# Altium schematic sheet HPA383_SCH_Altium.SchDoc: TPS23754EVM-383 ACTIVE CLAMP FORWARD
size 558 x 431 mm; CompanyName: TEXAS INSTRUMENTS; DrawnBy: Eric Wright; DocumentNumber: HPA383; Revision: B; SheetNumber: 1; SheetTotal: 1
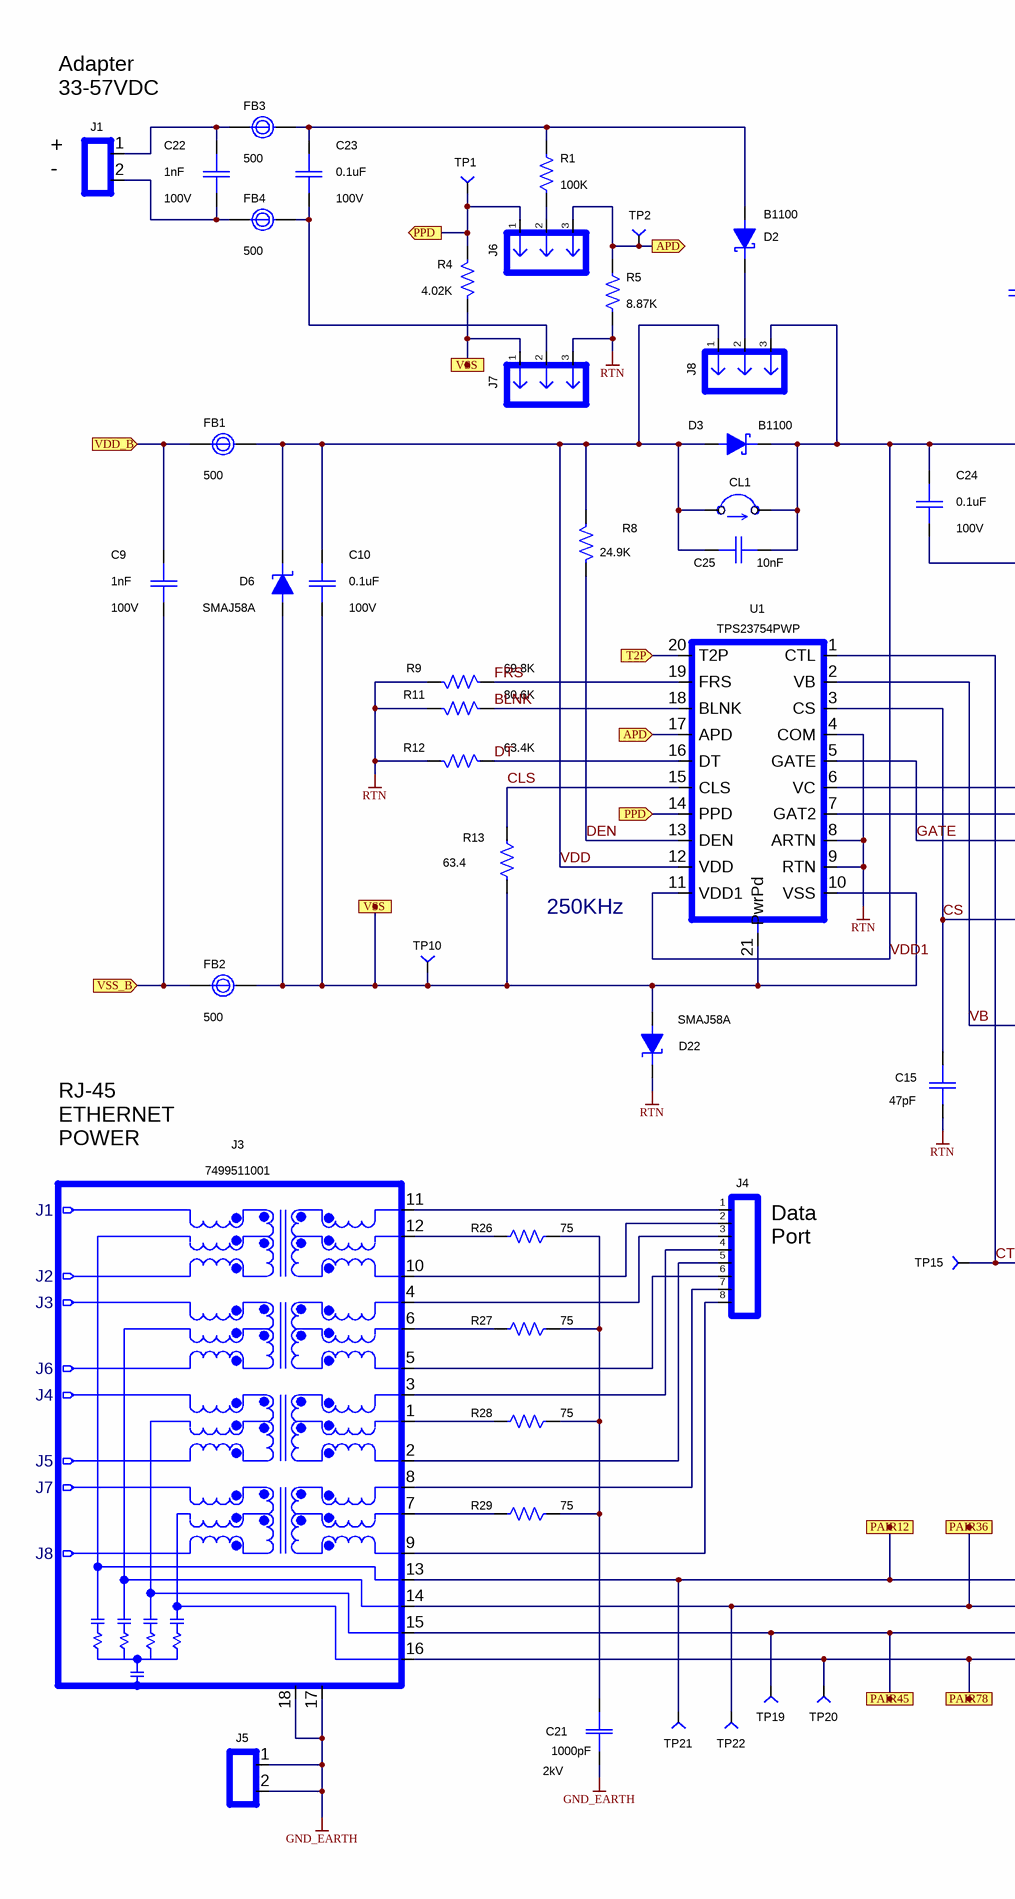
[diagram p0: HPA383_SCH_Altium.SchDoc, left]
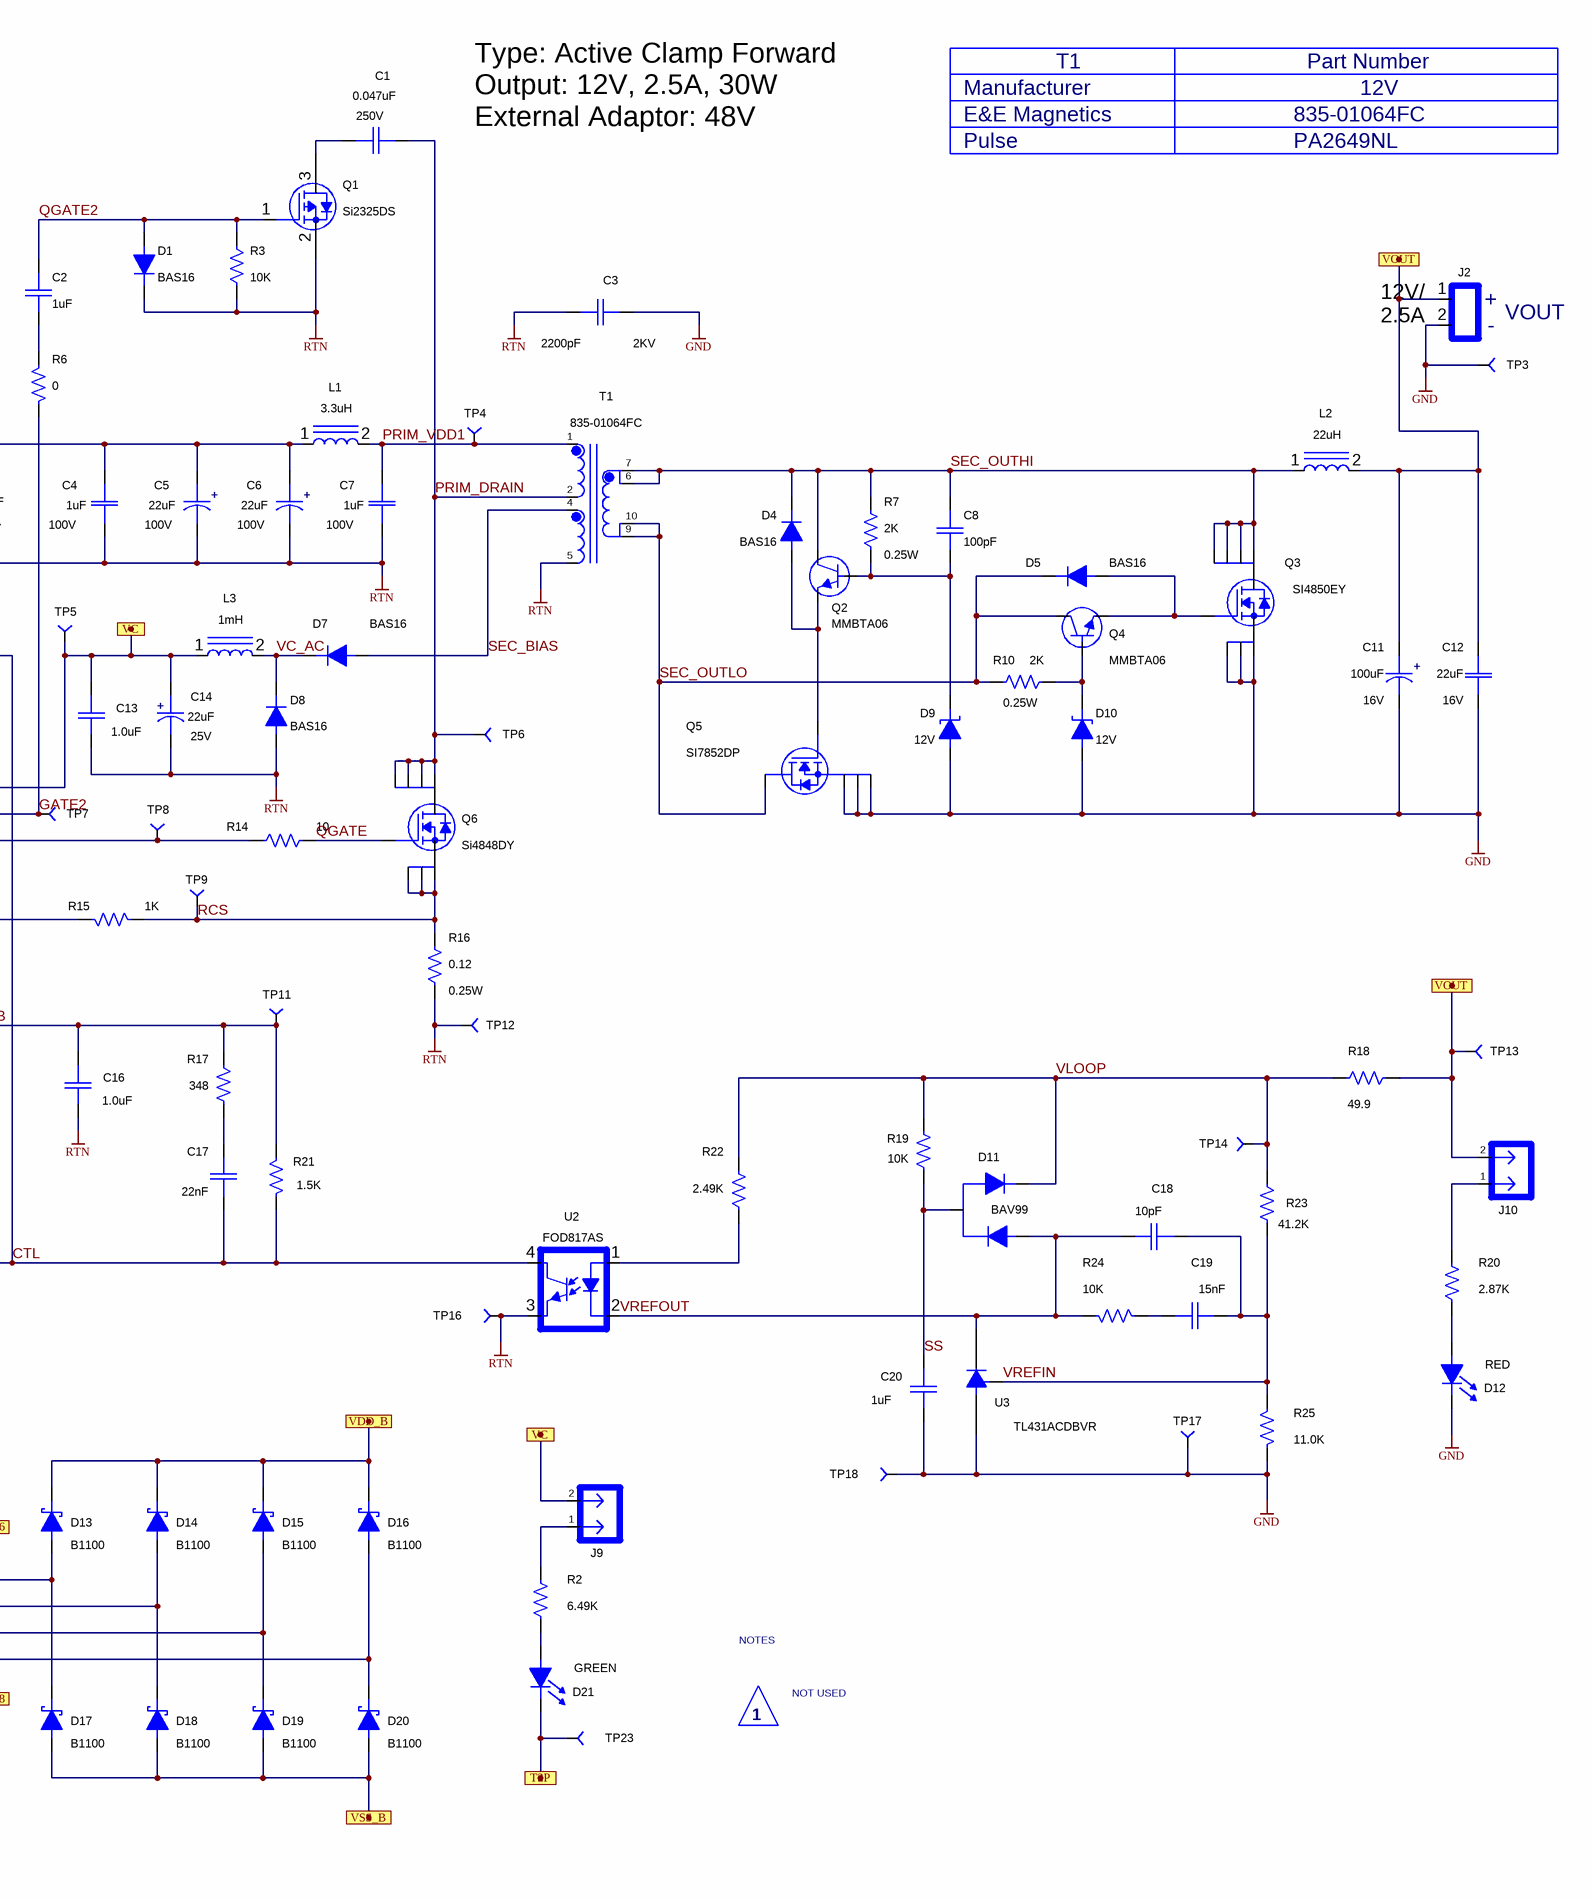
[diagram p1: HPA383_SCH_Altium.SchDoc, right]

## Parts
C1  value 0.047uF  Voltage: 250V  [C1206]  (hidden comment: C1206)
C2  value 1uF  [C603]  (hidden comment: C603)
C3  value 2200pF  Volts: 2KV  [C1812]  (hidden comment: C1812)
C4  value 1uF  Volts: 100V  [C1210]  (hidden comment: C1210)
C5  value 22uF  Volts: 100V  [CAP_ALUM_FK-F]  (hidden comment: CAP_ALUM_FK_F)
C6  value 22uF  Volts: 100V  [CAP_ALUM_FK-F]  (hidden comment: CAP_ALUM_FK_F)
C7  value 1uF  Volts: 100V  [C1210]  (hidden comment: C1210)
C8  value 100pF  [C603]  (hidden comment: C603)
C9  value 1nF  Volts: 100V  [C0805]  (hidden comment: C0805)
C10  value 0.1uF  Volts: 100V  [C0805]  (hidden comment: C0805)
C11  value 100uF  Voltage: 16V  [CAP_ALUM_FC-D]  (hidden comment: CAP_ALUM_FC-D)
C12  value 22uF  Voltage: 16V  [C1210]  (hidden comment: C1210)
C13  value 1.0uF  [C0805]  (hidden comment: C0805)
C14  value 22uF  Voltage: 25V  [CAP_ALUM_FK-C]  (hidden comment: CAP_ALUM_FK_C)
C15  value 47pF  [C603]  (hidden comment: C603)
C16  value 1.0uF  [C603]  (hidden comment: C603)
C17  value 22nF  [C603]  (hidden comment: C603)
C18  value 10pF  [C603]  (hidden comment: C603)
C19  value 15nF  [C603]  (hidden comment: C603)
C20  value 1uF  [C0805]  (hidden comment: C0805)
C21  value 1000pF  Voltage: 2kV  [C1210]  (hidden comment: C1210)
C22  value 1nF  Volts: 100V  [C0805]  (hidden comment: C0805)
C23  value 0.1uF  Volts: 100V  [C0805]  (hidden comment: C0805)
C24  value 0.1uF  Volts: 100V  [C0805]  (hidden comment: C0805)
C25  value 10nF  [C603]  (hidden comment: C603)
CL1  CURLOOP_25MIL-DIA  [CURLOOP_25-DIA]  (value not drawn)
D1  value BAS16  [SOT-23]  (hidden comment: D-BAS16)
D2  value B1100  [DIODE_SMA]  (hidden comment: D_SCHOT_SMA)
D3  value B1100  [DIODE_SMA]  (hidden comment: D_SCHOT_SMA)
D4  value BAS16  [SOT-23]  (hidden comment: D-BAS16)
D5  value BAS16  [SOT-23]  (hidden comment: D-BAS16)
D6  value SMAJ58A  [DIODE_SMA]  (hidden comment: D_ZENER_SMAZ15)
D7  value BAS16  [SOT-23]  (hidden comment: D-BAS16)
D8  value BAS16  [SOT-23]  (hidden comment: D-BAS16)
D9  value 12V  [SOT-23]  (hidden comment: D_ZENER_SOT23)
D10  value 12V  [SOT-23]  (hidden comment: D_ZENER_SOT23)
D11  value BAV99  [SOT-23]  (hidden comment: D-BAV99)
D12  value RED  [LED-1210]  (hidden comment: D_LED_1210)
D13  value B1100  [DIODE_SMA]  (hidden comment: D_SCHOT_SMA)
D14  value B1100  [DIODE_SMA]  (hidden comment: D_SCHOT_SMA)
D15  value B1100  [DIODE_SMA]  (hidden comment: D_SCHOT_SMA)
D16  value B1100  [DIODE_SMA]  (hidden comment: D_SCHOT_SMA)
D17  value B1100  [DIODE_SMA]  (hidden comment: D_SCHOT_SMA)
D18  value B1100  [DIODE_SMA]  (hidden comment: D_SCHOT_SMA)
D19  value B1100  [DIODE_SMA]  (hidden comment: D_SCHOT_SMA)
D20  value B1100  [DIODE_SMA]  (hidden comment: D_SCHOT_SMA)
D21  value GREEN  [LED-1210]  (hidden comment: D_LED_1210)
D22  value SMAJ58A  [DIODE_SMA]  (hidden comment: D_ZENER_SMAZ15)
FB1  value 500  [1206]  (hidden comment: BEAD-MI1206K900R-10)
FB2  value 500  [1206]  (hidden comment: BEAD-MI1206K900R-10)
FB3  value 500  [1206]  (hidden comment: BEAD-MI1206K900R-10)
FB4  value 500  [1206]  (hidden comment: BEAD-MI1206K900R-10)
J1  TBLK_6A_2X3.5MM  [TB_2X3.5MM]  (value not drawn)
J2  TBLK_6A_2X3.5MM  [TB_2X3.5MM]  (value not drawn)
J3  value 7499511001  [JACK_7499511001]  (hidden comment: CONN_J45_7499511001)
J4  CONN_JACK_556416  [JACK_MODULAR-FLANGELESS]  (value not drawn)
J5  TBLK_6A_2X3.5MM  [TB_2X3.5MM]  (value not drawn)
J6  HEADER_1X3  [HDR100_1X3]  (value not drawn)
J7  HEADER_1X3  [HDR100_1X3]  (value not drawn)
J8  HEADER_1X3  [HDR100_1X3]  (value not drawn)
J9  HEADER_1X2  [HDR100_1X2]  (value not drawn)
J10  HEADER_1X2  [HDR100_1X2]  (value not drawn)
L1  value 3.3uH  [MSS5131]  (hidden comment: IND_MSS5131 SERIES)
L2  value 22uH  [IND_P1173]  (hidden comment: IND_P1173)
L3  value 1mH  [IND_LPS170X170]  (hidden comment: IND_LPS4414 SERIES)
Q1  value Si2325DS  [SOT-23]  (hidden comment: TR-NDS0605)
Q2  value MMBTA06  [SOT-23]  (hidden comment: TR_NPN_SOT23)
Q3  value SI4850EY  [SO8]  (hidden comment: TR-SI4850EY)
Q4  value MMBTA06  [SOT-23]  (hidden comment: TR_NPN_SOT23)
Q5  value SI7852DP  [SO8-PWP]  (hidden comment: TR-SI7850DP)
Q6  value Si4848DY  [SO8]  (hidden comment: TR-SI4888DY)
R1  value 100K  [R603]  (hidden comment: R603)
R2  value 6.49K  [R0805]  (hidden comment: R0805)
R3  value 10K  [R603]  (hidden comment: R603)
R4  value 4.02K  [R603]  (hidden comment: R603)
R5  value 8.87K  [R603]  (hidden comment: R603)
R6  value 0  [R603]  (hidden comment: R603)
R7  value 2K  Power: 0.25W  [R1210]  (hidden comment: R1210)
R8  value 24.9K  [R603]  (hidden comment: R603)
R9  value 69.8K  [R603]  (hidden comment: R0603_1%)
R10  value 2K  Power: 0.25W  [R1210]  (hidden comment: R1210)
R11  value 80.6K  [R603]  (hidden comment: R0603_1%)
R12  value 63.4K  [R603]  (hidden comment: R603)
R13  value 63.4  [R0805]  (hidden comment: R0805_1%)
R14  value 10  [R603]  (hidden comment: R603)
R15  value 1K  [R603]  (hidden comment: R603)
R16  value 0.12  Power: 0.25W  [R1206]  (hidden comment: R1206_1%)
R17  value 348  [R603]  (hidden comment: R603)
R18  value 49.9  [R603]  (hidden comment: R603)
R19  value 10K  [R603]  (hidden comment: R603)
R20  value 2.87K  [R0805]  (hidden comment: R0805)
R21  value 1.5K  [R603]  (hidden comment: R603)
R22  value 2.49K  [R603]  (hidden comment: R603)
R23  value 41.2K  [R603]  (hidden comment: R603)
R24  value 10K  [R603]  (hidden comment: R603)
R25  value 11.0K  [R603]  (hidden comment: R603)
R26  value 75  [R603]  (hidden comment: R603)
R27  value 75  [R603]  (hidden comment: R603)
R28  value 75  [R603]  (hidden comment: R603)
R29  value 75  [R603]  (hidden comment: R603)
T1  value 835-01064FC  [XFMR_PA 524 X 685]  (hidden comment: XFMR_PA2328NL)
TP1  TP-5012-WHITE  [TH-63]  (value not drawn)
TP2  TP-5012-WHITE  [TH-63]  (value not drawn)
TP3  TP-5011-BLACK  [TH-63]  (value not drawn)
TP4  TP-5010-RED  [TH-63]  (value not drawn)
TP5  TP-5010-RED  [TH-63]  (value not drawn)
TP6  TP-5013-ORANGE  [TH-63]  (value not drawn)
TP7  TP-5012-WHITE  [TH-63]  (value not drawn)
TP8  TP-5012-WHITE  [TH-63]  (value not drawn)
TP9  TP-5012-WHITE  [TH-63]  (value not drawn)
TP10  TP-5011-BLACK  [TH-63]  (value not drawn)
TP11  TP-5010-RED  [TH-63]  (value not drawn)
TP12  TP-5011-BLACK  [TH-63]  (value not drawn)
TP13  TP-5010-RED  [TH-63]  (value not drawn)
TP14  TP-5013-ORANGE  [TH-63]  (value not drawn)
TP15  TP-5012-WHITE  [TH-63]  (value not drawn)
TP16  TP-5011-BLACK  [TH-63]  (value not drawn)
TP17  TP-5011-BLACK  [TH-63]  (value not drawn)
TP18  TP-5011-BLACK  [TH-63]  (value not drawn)
TP19  TP-5013-ORANGE  [TH-63]  (value not drawn)
TP20  TP-5010-RED  [TH-63]  (value not drawn)
TP21  TP-5013-ORANGE  [TH-63]  (value not drawn)
TP22  TP-5010-RED  [TH-63]  (value not drawn)
TP23  TP-5012-WHITE  [TH-63]  (value not drawn)
U1  TPS23754PWP  [PWP20]
U2  value FOD817AS  [SMT_4PDIP]  (hidden comment: OPTO_FOD817)
U3  value TL431ACDBVR  [SOT25]  (hidden comment: TLV431AIDBVR)

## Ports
APD (in), APD (out), PAIR12, PAIR36, PAIR45, PAIR78, PPD (in), PPD (out), T2P, T2P (in), VC, VDD_B, VDD_B (in), VOUT, VSS, VSS_B, VSS_B (in)

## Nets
GND: C3.1 C11.1 C12.1 C20.1 D9.1(A) D10.1(A) D12.1(C) J2.2 Q3.1(S) Q3.2(S) Q3.3(S) Q5.1(S) Q5.2(S) Q5.3(S) R25.2 TP3.1 TP17.1 TP18.1 U3.5(A)
GND_EARTH: C21.1 J3.17 J3.18 J5.1 J5.2
RTN: C3.2 C4.1 C5.2 C6.2 C7.1 C13.1 C14.2 C15.1 C16.1 C24.1 D1.3(A) D8.1(C) D22.1(C) J7.3 Q1.2(S) R3.2 R5.2 R9.2 R11.1 R12.1 R16.2 T1.5 TP12.1 TP16.1 U1.4(COM) U1.8(ARTN) U1.9(RTN) U2.3(E)
APD: J6.3 R5.1 TP2.1 U1.17(APD) ; port APD
BLNK: R11.2 U1.18(BLNK)
CLS: R13.1 U1.15(CLS)
CS: C15.2 R15.1 U1.3(CS)
CTL: C17.2 R21.2 TP15.1 U1.1(CTL) U2.4(C)
DEN: R8.2 U1.13(DEN)
DT: R12.2 U1.16(DT)
FRS: R9.1 U1.19(FRS)
GATE: R14.1 TP8.1 U1.5(GATE)
GATE2: R6.2 TP7.1 U1.7(GAT2)
PPD: J6.1 R4.1 TP1.1 U1.14(PPD) ; port PPD
PRIM_DRAIN: C1.1 Q6.5(D) Q6.6(D) Q6.7(D) Q6.8(D) T1.2 TP6.1
PRIM_VDD1: C7.2 L1.2 T1.1 TP4.1
QGATE: Q6.4(G) R14.2
QGATE2: C2.2 D1.1(C) Q1.1(G) R3.1
RCS: Q6.1(S) Q6.2(S) Q6.3(S) R15.2 R16.1 TP9.1
SEC_BIAS: D7.1(C) T1.4
SEC_OUTHI: C8.2 D4.3(A) L2.1 Q2.3(C) Q3.5(D) Q3.6(D) Q3.7(D) Q3.8(D) R7.1 T1.6 T1.7
SEC_OUTLO: D5.3(A) Q4.3(C) Q5.5(D) R10.1 T1.9 T1.10
SS: C20.2 D11.3(C) R19.2
T2P: U1.20(T2P) ; port T2P
VB: C16.2 R17.1 R21.1 TP11.1 U1.2(VB)
VC_AC: D7.3(A) D8.3(A) L3.2
VDD: C10.2 C25.2 CL1.1 D3.2(A) D6.1(C) FB1.2 J8.1 R8.1 U1.12(VDD)
VDD1: C4.2 C5.1 C6.1 C24.2 C25.1 CL1.2 D3.1(C) J8.3 L1.1 U1.11(VDD1)
VDD_B: C9.2 FB1.1 ; port VDD_B
VLOOP: D11.2(K2) R18.1 R19.1 R22.1 R23.1 TP14.1
VREFIN: C18.2 C19.1 R23.2 R25.1 U3.4(Ref)
VREFOUT: C18.1 D11.1(A1) R24.1 U2.2(K) U3.3(C)
VSS_B: C9.1 FB2.1 ; port VSS_B
NetC1_2: C1.2 Q1.3(D)
NetC2_1: C2.1 R6.1
NetC8_1: C8.1 D9.3(C) Q2.1(B) R7.2
NetC10_1: C10.1 D6.2(A) D22.2(A) FB2.2 R13.2 TP10.1 U1.10(VSS) U1.21(PwrPd)
NetC11_2: C11.2 C12.2 J2.1 L2.2
NetC13_2: C13.2 C14.1 L3.1 TP5.1 U1.6(VC)
NetC17_1: C17.1 R17.2
NetC19_2: C19.2 R24.2
NetC21_2: C21.2 R26.2 R27.2 R28.2 R29.2
NetC22_1: C22.1 FB4.1 J1.2
NetC22_2: C22.2 FB3.1 J1.1
NetC23_1: C23.1 FB4.2 J7.2
NetC23_2: C23.2 D2.2(A) FB3.2 R1.1
NetD2_1: D2.1(C) J8.2
NetD4_1: D4.1(C) Q2.2(E) Q5.4(G)
NetD5_1: D5.1(C) Q3.4(G) Q4.2(E)
NetD10_3: D10.3(C) Q4.1(B) R10.2
NetD12_2: D12.2(A) R20.2
NetD13_1: D13.1(C) D14.1(C) D15.1(C) D16.1(C)
NetD13_2: D13.2(A) D17.1(C) J3.13 TP21.1
NetD14_2: D14.2(A) D18.1(C) J3.14 TP22.1
NetD15_2: D15.2(A) D19.1(C) J3.15 TP19.1
NetD16_2: D16.2(A) D20.1(C) J3.16 TP20.1
NetD17_2: D17.2(A) D18.2(A) D19.2(A) D20.2(A)
NetD21_1: D21.1(C) TP23.1
NetD21_2: D21.2(A) R2.2
NetJ3_1: J3.1 R28.1
NetJ3_2: J3.2 J4.5
NetJ3_3: J3.3 J4.4
NetJ3_4: J3.4 J4.3
NetJ3_5: J3.5 J4.6
NetJ3_6: J3.6 R27.1
NetJ3_7: J3.7 R29.1
NetJ3_8: J3.8 J4.7
NetJ3_9: J3.9 J4.8
NetJ3_10: J3.10 J4.2
NetJ3_11: J3.11 J4.1
NetJ3_12: J3.12 R26.1
NetJ6_2: J6.2 R1.2
NetJ7_1: J7.1 R4.2
NetJ9_1: J9.1 R2.1
NetJ10_1: J10.1 R20.1
NetJ10_2: J10.2 R18.2 TP13.1
NetR22_2: R22.2 U2.1(A)

Not connected (* = marked no-connect by the designer): D1 2; D4 2; D5 2; D7 2; D8 2; D9 2; D10 2; J3 19 20; J4 9 10; J9 2; T1 3 8; U3 1 2

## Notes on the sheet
- Manufacturer
- T1
- Part Number
- 12V
- Adapter
  33-57VDC
- Type: Active Clamp Forward
  Output: 12V, 2.5A, 30W
  External Adaptor: 48V
- Pulse
- E&E Magnetics
- PA2649NL
- 835-01064FC
- (near J1) +
  -
- +
- (near J2) 12V/
  2.5A
- -
- VOUT
- 250KHz
- RJ-45
  ETHERNET
  POWER
- (near J4) Data
  Port
- NOTES
- NOT USED
- 1

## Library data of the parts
C1 = C1206: Capacitor, Ceramic, 250V, X7R, 10%; Manufacturer: Std; Area: 15390
C2 = C603_VARIANT_1: Capacitor, Ceramic, 16V, X7R, 20%; Manufacturer: TDK; PartNumber: C1608X7R1C105M; Area: 5650
C3 = C1812: Capacitor, Ceramic, 2KV, X7R, 10%; Manufacturer: TDK; PartNumber: C4532X7R3D222K; Area: 43,360
C4 C7 = C1210_VARIANT_2: Capacitor, Ceramic, 100V, X7R, 10%; Manufacturer: Std; Area: 83,600
C5 C6 = CAP_ALUM_FK_F: Capacitor, Aluminum, 100V, ±20%; Manufacturer: Panasonic; PartNumber: EEVFK2A220P; Area: 161,100
C8 = C603_VARIANT_1: Capacitor, Ceramic, 50V, X7R, 10%; Manufacturer: TDK; PartNumber: C1608X7R1H101K; Area: 5650
C9 C22 = C0805: Capacitor, Ceramic, 100V, X7R, 10%; Manufacturer: Std; Area: 10560
C10 C23 C24 = C0805: Capacitor, Ceramic, 100V,  X7R, 10%; Manufacturer: Std; Area: 10560
C11 = CAP_ALUM_FC-D: Capacitor, Aluminum, 16V, 20%, FK Series; Manufacturer: Panasonic; PartNumber: EEVFK1C101P; Area: 73,700
C12 = C1210: Capacitor, Ceramic, 16-V, X7R, 20%; Manufacturer: TDK; PartNumber: C3225X7R1C226MT; Area: 24200
C13 = C0805_VARIANT_1: Capacitor, Ceramic, 25V, X7R,  10%; Manufacturer: Std; Area: 10560
C14 = CAP_ALUM_FK_C: Capacitor, Aluminum, 25V, 20%; Manufacturer: Panasonic; PartNumber: EEVFK1E220R; Area: 66,700
C15 = C603: Capacitor, Ceramic, 50V, X7R, 10%; Manufacturer: Std; Area: 5650
C16 = C603: Capacitor, Ceramic, 16V, X7R, 10%; Manufacturer: Std; Area: 5650
C17 C19 = C603_VARIANT_1: Capacitor, Ceramic, 50V, X7R, 10%; Manufacturer: Std; Area: 5650
C18 = C603_VARIANT_2: Capacitor, Ceramic, 50V, C0G, 5%; Manufacturer: Std; Area: 5650
C20 = C0805_VARIANT_2: Capacitor, Ceramic, 16V, X7R, 10%; Manufacturer: Std; Area: 10560
C21 = C1210_VARIANT_1: Capacitor, Ceramic, 2kV, X7R, 10%; Manufacturer: TDK; PartNumber: Std; Area: 83,600
C25 = C603_VARIANT_3: Capacitor, Ceramic, 100V, X7R, 10%; Manufacturer: Std; Area: 5650
CL1 = CURLOOP_25MIL-DIA: Current Loop, 0.025 holes; Value: NA
D1 = D-BAS16: Diode, Switching, 75V, 200mA; Manufacturer: Vishay-Liteon; PartNumber: BAS16LT1; Area: 14105; Second Source: C:\program files\p-cad 2004\pcad_pdf's\bas16v.pdf
D2 = D_SCHOT_SMA_VARIANT_1: Diode, Schottky, 1A, 100V; Manufacturer: Diodes, Inc; Area: 29520
D3 D13-D20 = D_SCHOT_SMA: Diode, Schottky, 1A, 100V; Manufacturer: Diodes, Inc; Area: 29520
D4 D5 D7 D8 = D-BAS16_VARIANT_1: Diode, Switching, 75V, 200mA; Manufacturer: Vishay-Liteon; PartNumber: BAS16LT1; Area: 14105; Second Source: C:\program files\p-cad 2004\pcad_pdf's\bas16v.pdf
D6 = D_ZENER_SMAZ15_VARIANT_1: Diode, TVS, 58-V, 1W; Manufacturer: Diodes Inc.; Area: 37520; Second Source: \\vette02\pmp_pcb\pcad_pdf's\SMAZ15.pdf
D9 D10 = D_ZENER_SOT23: Diode, Zener, 12-V; Manufacturer: ON Semiconductor; PartNumber: BZX84C12LT1; Area: 14105
D11 = D-BAV99: Diode, Dual Ultra Fast, Series, 200-mA, 70-V; Manufacturer: Fairchild; Area: 14105; Second Source: C:\program files\p-cad 2004\pcad_pdf's\BAV99.pdf
D12 = D_LED_1210: Diode, LED, RED, 2.0-V, 850-mcd,SM; Manufacturer: LITE-ON INC; PartNumber: LTST-C930KRKT; Area: 24976
D21 = D_LED_1210: Diode, LED, GRN, 2.0-V, 650-mcd,SM; Manufacturer: LITE-ON INC; PartNumber: LTST-C930KGKT; Area: 24976
D22 = D_ZENER_SMAZ15: Diode, TVS, 58-V, 1W; Manufacturer: Diodes Inc.; Area: 37520; Second Source: \\vette02\pmp_pcb\pcad_pdf's\SMAZ15.pdf
FB1-FB4 = BEAD-MI1206K900R-10: Bead, Ferrite, 2000mA, 60m-ohm; Manufacturer: Steward; PartNumber: MI1206L501R-10; Area: 38080
J1 J2 J5 = TBLK_6A_2X3.5MM: Terminal Block, 2-pin, 6-A, 3.5mm; Manufacturer: OST; Value: ED555/2DS; Area: 70125; Second Source: C:\program files\p-cad 2004\pcad_pdf's\ED555DS.pdf
J3 = CONN_J45_7499511001: Connector, RJ45, PoE+ Enabled, 1000 Base-T; Manufacturer: Wuerth Electronics; Area: 945000; Second Source: C:\program files\p-cad 2004\pcad_pdf's\7499511001.PDF
J4 = CONN_JACK_556416: Connector,  Jack Modular, Vertical, Pos.; Manufacturer: AMP; Value: 5556416-1
J6-J8 = HEADER_1X3: Header, Male 3-pin, 100mil spacing,; Manufacturer: Sullins; Value: PEC03SAAN; Area: 30000; Second Source: C:\program files\p-cad 2004\pcad_pdf's\pec36saan.pdf
J9 J10 = HEADER_1X2: Header, Male 2-pin, 100mil spacing,; Manufacturer: Sullins; Value: PEC02SAAN; Area: 20000; Second Source: C:\program files\p-cad 2004\pcad_pdf's\pec36saan.pdf
L1 = IND_MSS5131 SERIES: Inductor, SMT, 1.53A, 32milliohm; Manufacturer: Coilcraft; PartNumber: MSS5131-332MX; Area: 65
L2 = IND_P1173: Inductor, SMT, 3.8A, 33-milliohm; Manufacturer: Pulse Magnetics; PartNumber: P1173.223T; Area: 250000
L3 = IND_LPS4414 SERIES: Inductor, SMT, 100mA, 16.3 ohm; Manufacturer: Coilcraft; PartNumber: LPS4414-105MLC; Area: 52900; Second Source: C:\program files\p-cad 2004\pcad_pdf's\lps4414.pdf
Q1 = TR-NDS0605: MOSFET,P-ch, -150 V, 690-mA, 1.2 Ohms; Manufacturer: Vishay; Area: 30,600
Q2 = TR_NPN_SOT23: Bipolar, NPN, 80V, 500mA; PartNumber: MMBTA06LT1; Manufacturer: ON Semiconductor; Area: 14105
Q3 = TR-SI4850EY: MOSFET, Nch, 60V, 8.5A, 22milliohm; Manufacturer: Vishay; Area: 75900; Second Source: C:\program files\p-cad 2004\pcad_pdf's\Si4850.pdf
Q4 = TR_NPN_SOT23_VARIANT_1: Bipolar, NPN, 80V, 500mA; PartNumber: MMBTA06LT1; Manufacturer: ON Semiconductor; Area: 14105
Q5 = TR-SI7850DP: MOSFET, NChan, 80V, 12A, 16-millohm; Manufacturer: Vishay; AREA: 85057; Second Source: C:\program files\p-cad 2004\pcad_pdf's\Si7850DP.pdf
Q6 = TR-SI4888DY: MOSFET, N-ch, 150V, 3.7A, 85 milliohm; Manufacturer: Vishay; Area: 75,900
R1 R4-R6 R8 R17 R19 R21-R23 R25 = R603: Resistor, Chip, 1/16W, 1%; PartNumber: Std; Area: 5650
R2 R20 = R0805: Resistor, Chip, 1/10-W, 1%; PartNumber: Std; Area: 10560
R3 R14 R18 = R603_VARIANT_2: Resistor, Chip, 1/16W, 1%; PartNumber: Std; Area: 5650
R7 = R1210_VARIANT_1: Resistor, Chip, 1/4W, 5%; PartNumber: Std; Area: 24200
R9 = R0603_1%_VARIANT_1: Resistor, Chip, 1/16W, 1%; PartNumber: Std; Area: 9100
R10 = R1210: Resistor, Chip, 1/4W, 5%; PartNumber: Std; Area: 24200
R11 = R0603_1%: Resistor, Chip, 1/16W, 1%; PartNumber: Std; Area: 9100
R12 R15 R24 = R603_VARIANT_1: Resistor, Chip, 1/16W, 1%; PartNumber: Std; Area: 5650
R13 = R0805_1%: Resistor, Chip, 1/10W, 1%; PartNumber: Std; Area: 15,300
R16 = R1206_1%: Resistor, Chip, 1/4W, 1%; PartNumber: ERJ-8RQFR12V; Manufacturer: Panasonic ECG; Area: 20,000
R26-R29 = R603_VARIANT_2: Resistor, Chip, 1/16W, 1%; PartNumber: Std; Area: 5,650
T1 = XFMR_PA2328NL: Transformer, forward, 100uH, 12V, 2.5A; Manufacturer: E&E Magnetics; Area: 425600; Second Source: C:\program files\p-cad 2004\pcad_pdf's\PA2328NLrevX1.pdf
TP1 TP2 TP7-TP9 TP15 TP23 = TP-5012-WHITE: Test Point,  White, Thru Hole; Manufacturer: Keystone; Value: 5012; Second Source: C:\program files\p-cad 2004\pcad_pdf's\Keystone-SMT-TH_Test point.pdf
TP3 TP10 TP12 TP16-TP18 = TP-5011-BLACK: Test Point,  Black, Thru Hole; Manufacturer: Keystone; Value: 5011; Second Source: C:\program files\p-cad 2004\pcad_pdf's\Keystone-SMT-TH_Test point.pdf
TP4 TP5 TP11 TP13 TP20 TP22 = TP-5010-RED: Test Point,  Red, Thru Hole; Manufacturer: Keystone; Value: 5010; Second Source: C:\program files\p-cad 2004\pcad_pdf's\Keystone-SMT-TH_Test point.pdf
TP6 TP14 TP19 TP21 = TP-5013-ORANGE: Test Point,  Orange, Thru Hole; Manufacturer: Keystone; Value: 5013; Second Source: C:\program files\p-cad 2004\pcad_pdf's\Keystone-SMT-TH_Test point.pdf
U1 = TPS23754PWP: IC, IEEE 802.3at PoE Interface and Isolated Converter Controller; Manufacturer: TI; Alternate Manufacturer: None; Area: 96000; Second Source: C:\program files\p-cad 2004\pcad_pdf's\TPS23754 CDS 12_27_07.doc
U2 = OPTO_FOD817: IC, Optocoupler, 6-V, 80-160% CTR; Manufacturer: Fairchild; Area: 100320; Second source: C:\program files\p-cad 2004\pcad_pdf's\FOD817.pdf
U3 = TLV431AIDBVR: IC, Shunt Regulator, 2.49-V ref, 36-V, 10-mA, 1%; Manufacturer: TI; Alternate Manufacturer: None; Area: 16384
